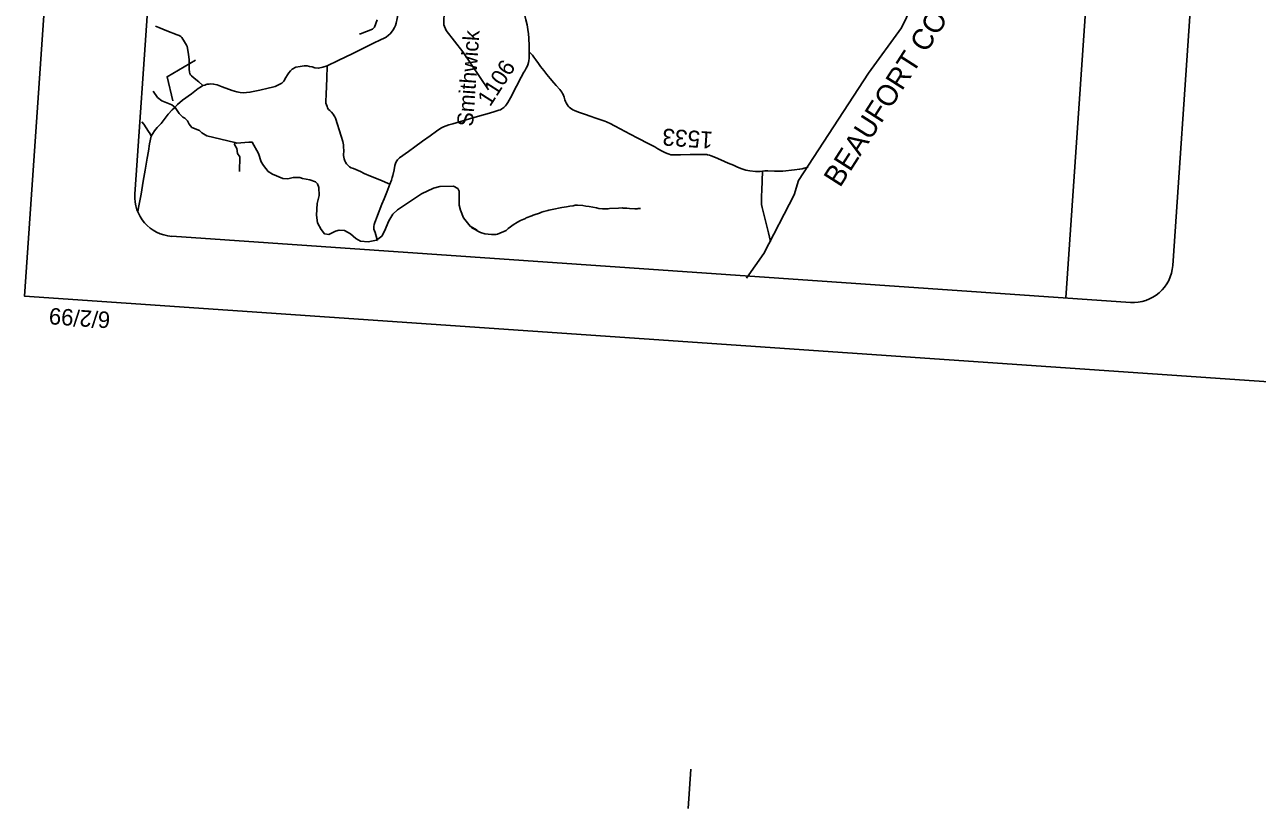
# Model space of a CAD drawing. Extents: x 2599057 to 2600057, y 728628 to 732947.
# Drawn here: x 2599056.6 to 2599398.7, y 731487.8 to 731705.3 of the extents above; entities that cross this region are included whole.
import ezdxf

# ---------------------------------------------------------------- set-up
doc = ezdxf.new("R2010")
doc.units = 0
for name, color, linetype in [('CTL Sheet Border CELL', 7, 'Continuous'), ('Old_Level_1', 7, 'Continuous'), ('Old_Level_31', 7, 'Continuous'), ('Old_Level_32', 7, 'Continuous'), ('Old_Level_50', 7, 'Continuous'), ('Old_Level_59', 7, 'Continuous')]:
    doc.layers.add(name, color=color, linetype=linetype)

msp = doc.modelspace()

# ---------------------------------------------------------------- linework, layer by layer
at = {"layer": 'CTL Sheet Border CELL'}
msp.add_line((2599240.76, 731487.81), (2599241.5, 731498.65), dxfattribs=at)
msp.add_lwpolyline([(2599146.23, 732931.19), (2599056.61, 731629.92), (2599967.49, 731567.19), (2600057.11, 732868.45)], close=True, dxfattribs=at)
at = {"layer": 'Old_Level_1'}
for p, q in [((2599108.17, 731962.68), (2599087.2, 731658.27)), ((2599345.52, 731629.45), (2599368, 731955.82)), ((2599375.24, 731638.43), (2599396.21, 731942.85)), ((2599307.81, 731720.71), (2599299.92, 731704.42)), ((2599299.92, 731704.42), (2599290.83, 731691.79)), ((2599290.83, 731691.79), (2599271.37, 731662.02)), ((2599271.37, 731662.02), (2599270.13, 731658.02)), ((2599270.13, 731658.02), (2599261.76, 731641.77)), ((2599097.42, 731646.54), (2599363.51, 731628.21)), ((2599261.76, 731641.77), (2599256.94, 731634.96))]:
    msp.add_line(p, q, dxfattribs=at)
for centre, start, end in [((2599098.18, 731657.51), 176.0601, 266.06), ((2599364.27, 731639.19), 266.06, 356.0601)]:
    msp.add_arc(centre, 11, start, end, dxfattribs=at)
at = {"layer": 'Old_Level_31'}
for p, q in [((2599098.42, 731682.31), (2599098.42, 731682.31)), ((2599261.31, 731654.36), (2599261.31, 731654.36)), ((2599154.58, 731645.25), (2599154.58, 731645.25))]:
    msp.add_line(p, q, dxfattribs=at)
msp.add_lwpolyline([(2599103.99, 731695.39), (2599096.12, 731690.83), (2599097.75, 731684.18)], dxfattribs=at)
at = {"layer": 'Old_Level_32'}
for points in [[(2599140.59, 731693.84), (2599143.66, 731695.37), (2599147.67, 731697.29), (2599153.26, 731700.01), (2599155.53, 731701.14), (2599156.17, 731701.43), (2599156.91, 731701.83), (2599157.58, 731702.32), (2599158.02, 731702.72), (2599158.41, 731703.19), (2599158.89, 731703.86), (2599159.24, 731704.46), (2599159.5, 731705.08), (2599159.69, 731705.69), (2599159.98, 731706.95), (2599160.47, 731709.67), (2599160.85, 731711.34), (2599161.37, 731713.02), (2599161.68, 731713.91)], [(2599195.11, 731708.64), (2599195.39, 731707.85), (2599195.71, 731706.65), (2599196.04, 731705.25), (2599196.3, 731703.93), (2599196.46, 731702.75), (2599196.54, 731701.57), (2599196.59, 731699.4), (2599196.62, 731697.78)], [(2599092.93, 731704.84), (2599093.86, 731704.47), (2599096.07, 731703.55), (2599098.89, 731702.48), (2599099.5, 731702.24), (2599099.93, 731701.98), (2599100.21, 731701.71), (2599101, 731700.47), (2599101.56, 731699.56), (2599101.71, 731699.17), (2599101.82, 731698.73), (2599102.11, 731697.04), (2599102.24, 731695.62), (2599102.29, 731694.35), (2599102.29, 731692.96), (2599102.35, 731692.08), (2599102.45, 731691.74), (2599102.62, 731691.38), (2599102.91, 731691.05), (2599103.61, 731690.47), (2599104.93, 731689.39), (2599106.04, 731688.37)], [(2599196.62, 731697.78), (2599196.64, 731695.95), (2599196.57, 731695.28), (2599196.47, 731694.75), (2599196.28, 731694.16), (2599196.07, 731693.67), (2599195.82, 731693.21), (2599195.46, 731692.5), (2599195.17, 731692.05), (2599194.44, 731690.68), (2599193.15, 731688.23), (2599191.42, 731684.95), (2599190.69, 731683.68), (2599190.36, 731683.13), (2599190.07, 731682.76), (2599189.62, 731682.3), (2599189.36, 731682.11), (2599189.03, 731681.91), (2599188.65, 731681.68), (2599188.23, 731681.51), (2599186.81, 731681.1), (2599185.01, 731680.56), (2599182.92, 731679.94), (2599180.09, 731679.13), (2599175.4, 731677.77), (2599174.35, 731677.44), (2599173.62, 731677.17), (2599172.85, 731676.89), (2599172.12, 731676.52), (2599170.93, 731675.69), (2599169.18, 731674.44), (2599167.02, 731672.91), (2599164.93, 731671.4), (2599163.1, 731670.08), (2599160.65, 731668.32), (2599160.35, 731668.07), (2599160.12, 731667.8), (2599159.91, 731667.49), (2599159.72, 731667.17), (2599159.55, 731666.77), (2599159.38, 731666.16), (2599159.12, 731665.03), (2599158.77, 731663.43), (2599158.64, 731662.88), (2599158.43, 731662.16), (2599157.94, 731661.02)], [(2599196.62, 731697.78), (2599196.92, 731697.46), (2599197.55, 731696.8), (2599197.96, 731696.26), (2599198.45, 731695.56), (2599199.18, 731694.52), (2599199.8, 731693.67), (2599200.66, 731692.58), (2599201.56, 731691.49), (2599202.49, 731690.38), (2599203.51, 731689.14), (2599204.13, 731688.42), (2599205.12, 731687.24), (2599205.65, 731686.52), (2599205.88, 731686.2), (2599206.05, 731685.86), (2599206.3, 731685.2), (2599206.53, 731684.42), (2599206.71, 731683.95), (2599206.89, 731683.55), (2599207.18, 731683.09), (2599207.46, 731682.7), (2599207.75, 731682.38), (2599208.06, 731682.08), (2599208.76, 731681.63), (2599209.25, 731681.41), (2599210.29, 731681), (2599212.23, 731680.35), (2599213.57, 731679.87), (2599215.17, 731679.32), (2599217.64, 731678.45), (2599218.12, 731678.29), (2599218.48, 731678.12), (2599218.9, 731677.93), (2599220.45, 731677.13), (2599224.7, 731674.89), (2599226.81, 731673.8), (2599228.11, 731673.12), (2599228.55, 731672.87), (2599229.69, 731672.28), (2599231.47, 731671.34), (2599232.35, 731670.82), (2599233.58, 731670.16), (2599234.25, 731669.82), (2599234.88, 731669.5), (2599235.46, 731669.31), (2599235.97, 731669.19), (2599236.44, 731669.12), (2599237.23, 731669.11), (2599238.66, 731669.14), (2599241.31, 731669.2), (2599243.56, 731669.26), (2599244.78, 731669.27), (2599245.42, 731669.26), (2599245.91, 731669.22), (2599246.13, 731669.19), (2599246.64, 731669.08), (2599247.11, 731668.9), (2599248.32, 731668.44), (2599249.79, 731667.81), (2599251.89, 731666.87), (2599253.37, 731666.25), (2599254.3, 731665.84), (2599254.89, 731665.58), (2599255.61, 731665.3), (2599256.18, 731665.09), (2599256.73, 731664.94), (2599257.88, 731664.74), (2599259.46, 731664.52), (2599260.71, 731664.5), (2599261.39, 731664.6)], [(2599106.04, 731688.37), (2599106.57, 731688.51), (2599106.94, 731688.63), (2599107.27, 731688.72), (2599107.84, 731688.78), (2599108.27, 731688.82), (2599109.05, 731688.79), (2599110.08, 731688.59), (2599111.4, 731688.04), (2599114.17, 731687.03), (2599115.48, 731686.67), (2599116.42, 731686.45), (2599117.34, 731686.39), (2599118.2, 731686.41), (2599119.11, 731686.5), (2599120.01, 731686.7), (2599121.86, 731687.09), (2599124.17, 731687.65), (2599125.39, 731687.89), (2599126.14, 731688.09), (2599126.69, 731688.38), (2599127.25, 731688.63), (2599127.94, 731689.06), (2599128.5, 731689.64), (2599129.08, 731690.61), (2599129.55, 731691.35), (2599129.97, 731691.88), (2599130.38, 731692.47), (2599130.83, 731692.91), (2599131.85, 731693.47), (2599133.1, 731693.7), (2599134.14, 731693.81), (2599134.97, 731693.82), (2599135.65, 731693.71), (2599136.39, 731693.53), (2599137.16, 731693.31), (2599138.16, 731693.16), (2599139.32, 731693.49), (2599140.59, 731693.84)], [(2599157.94, 731661.02), (2599155.16, 731662.22), (2599152.6, 731663.26), (2599150.86, 731664.01), (2599149.81, 731664.49), (2599147.87, 731665.33), (2599147.22, 731665.59), (2599146.8, 731665.84), (2599146.46, 731666.12), (2599146.2, 731666.36), (2599145.95, 731666.61), (2599145.66, 731667.1), (2599145.46, 731667.47), (2599145.26, 731668.01), (2599145.17, 731668.46), (2599145.13, 731668.99), (2599145.15, 731670.46), (2599145.13, 731671.15), (2599145.09, 731671.95), (2599144.87, 731672.89), (2599144.47, 731674.3), (2599142.85, 731679.33), (2599142.71, 731679.74), (2599142.51, 731680.01), (2599142.25, 731680.4), (2599141.73, 731681.01), (2599141.26, 731681.48), (2599140.98, 731681.77), (2599140.7, 731682.2), (2599140.52, 731682.59), (2599140.34, 731683.06), (2599140.24, 731683.49), (2599140.19, 731683.94), (2599140.28, 731685.96), (2599140.44, 731690.32), (2599140.59, 731693.84)], [(2599098.24, 731682.19), (2599099.06, 731683.08), (2599100.39, 731684.32), (2599102.93, 731686.11), (2599104.74, 731687.53), (2599105.4, 731687.96), (2599106.04, 731688.37)], [(2599091.69, 731674.35), (2599092.65, 731675.85), (2599093.4, 731676.72), (2599094.5, 731677.89), (2599095.56, 731679.33), (2599096.4, 731680.41), (2599097.58, 731681.6), (2599098.21, 731682.15), (2599098.24, 731682.19)], [(2599091.69, 731674.35), (2599091.41, 731675.01), (2599090.99, 731675.6), (2599089.64, 731677.68), (2599089.17, 731678.31)], [(2599089.54, 731661.86), (2599090.04, 731664.87), (2599090.6, 731668.27), (2599090.94, 731670.14), (2599091.28, 731672.18), (2599091.69, 731674.35)], [(2599261.39, 731664.6), (2599261.18, 731659.22), (2599261.14, 731657.75)], [(2599261.39, 731664.6), (2599262.02, 731664.69), (2599262.82, 731664.74), (2599264.74, 731664.66), (2599266.26, 731664.59), (2599267.06, 731664.63), (2599267.86, 731664.69), (2599269.44, 731664.87), (2599270.3, 731665), (2599271.65, 731665.15), (2599272.43, 731665.31), (2599272.97, 731665.41), (2599274.09, 731665.72)], [(2599088.02, 731653.3), (2599088.22, 731654.55), (2599088.93, 731658.23), (2599089.54, 731661.86)], [(2599157.94, 731661.02), (2599157.08, 731658.78), (2599156.34, 731656.92), (2599155.77, 731655.48), (2599154.52, 731652.29), (2599153.95, 731650.88), (2599153.76, 731650.38), (2599153.57, 731649.78), (2599153.49, 731649.29), (2599153.49, 731648.86), (2599153.52, 731648.53), (2599153.85, 731647.58), (2599154.37, 731645.96), (2599154.54, 731645.41)], [(2599261.14, 731657.75), (2599261.13, 731657.31), (2599261.09, 731656.24), (2599261.13, 731655.4), (2599261.3, 731654.57), (2599262.04, 731651.6), (2599263.03, 731647.53), (2599263.59, 731645.13)]]:
    msp.add_lwpolyline(points, dxfattribs=at)
at = {"layer": 'Old_Level_50'}
for p, q in [((2599098.39, 731682.29), (2599098.39, 731682.29)), ((2599154.6, 731645.14), (2599154.6, 731645.14))]:
    msp.add_line(p, q, dxfattribs=at)
at = {"layer": 'Old_Level_59'}
for p, q in [((2599114.91, 731672.55), (2599107.21, 731674.38)), ((2599182.22, 731648.22), (2599180.21, 731649.32))]:
    msp.add_line(p, q, dxfattribs=at)
for points in [[(2599185.3, 731687.22), (2599178.2, 731697.74), (2599173.6, 731703.61), (2599172.9, 731705.21), (2599172.94, 731707.16), (2599173.41, 731709.05), (2599174.37, 731710.5), (2599176.01, 731712.22), (2599178.01, 731712.18), (2599179.67, 731713.49), (2599180.59, 731714.79), (2599181.22, 731716.89), (2599182, 731720.65), (2599182.43, 731721.75), (2599182.64, 731721.96)], [(2599154.43, 731706.6), (2599153.68, 731704.62), (2599153.12, 731704.04), (2599149.83, 731702.69), (2599149.52, 731702.7)], [(2599107.21, 731674.38), (2599105.82, 731675.23), (2599105.11, 731675.88), (2599103.03, 731676.77), (2599102.29, 731677.7), (2599101.82, 731678.61), (2599101.05, 731679.32), (2599100.47, 731679.62), (2599099.52, 731680.62), (2599098.39, 731682.3), (2599097.47, 731683.07), (2599094.67, 731684.1), (2599093.49, 731685.05), (2599092.25, 731686.79)], [(2599116.25, 731664.49), (2599116.36, 731668.57), (2599115.65, 731669.5), (2599115.47, 731670.91), (2599114.84, 731672.05), (2599114.91, 731672.55)], [(2599133.76, 731662.63), (2599132.96, 731662.9), (2599131.17, 731662.88), (2599129.62, 731662.51), (2599128.24, 731662.57), (2599125.38, 731663.83), (2599124.16, 731664.56), (2599122.85, 731666.19), (2599122.28, 731667.22), (2599121.53, 731669.5), (2599119.79, 731672.65), (2599118.84, 731672.7), (2599115.49, 731672.41), (2599114.91, 731672.55)], [(2599180.21, 731649.32), (2599178.42, 731651.7), (2599177.53, 731653.81), (2599177.22, 731655.23), (2599177.21, 731659.09), (2599176.82, 731659.84), (2599175.63, 731660.45), (2599171.87, 731660.41), (2599170.04, 731659.88), (2599166.78, 731658.3), (2599160.04, 731653.93), (2599158.82, 731652.7), (2599157.72, 731650.8), (2599156.51, 731648), (2599155.69, 731646.59), (2599154.26, 731645.43), (2599151.91, 731645.04), (2599149.86, 731645.2), (2599148.56, 731645.93), (2599147.08, 731647.23), (2599145.34, 731648.15), (2599143.86, 731648.28), (2599142.89, 731647.93), (2599141.03, 731647.01), (2599139.79, 731647.25), (2599138.88, 731648.4), (2599137.92, 731650.24), (2599137.65, 731652.38), (2599137.81, 731655.67), (2599138.3, 731657.89), (2599138.26, 731660.13), (2599137.87, 731661.09), (2599137.33, 731661.62), (2599135.72, 731662.2), (2599133.76, 731662.63)], [(2599222.69, 731654.4), (2599222.4, 731654.43), (2599221.42, 731654.32), (2599218.95, 731654.24), (2599218.53, 731654.2), (2599217.8, 731654.13), (2599217, 731654.13), (2599215.97, 731654.27), (2599215.31, 731654.49), (2599213.26, 731654.86), (2599212.36, 731654.91), (2599211.5, 731655.12), (2599210, 731655.18), (2599209.84, 731655.16), (2599209.43, 731655.17), (2599208.87, 731655.04), (2599207.94, 731654.9), (2599206.98, 731654.69), (2599205.72, 731654.52), (2599203.04, 731654.01), (2599202.1, 731653.82), (2599201.84, 731653.7), (2599200.67, 731653.46), (2599200.05, 731653.27), (2599199.45, 731653), (2599197.98, 731652.47), (2599197.71, 731652.4), (2599197.34, 731652.19), (2599195.81, 731651.64), (2599195.6, 731651.51), (2599194.24, 731650.93), (2599193.35, 731650.49), (2599192.21, 731649.75), (2599191.4, 731649.17), (2599190.79, 731648.72), (2599190.21, 731648.18), (2599187.87, 731647.14), (2599187.4, 731647.04), (2599186.13, 731647.05), (2599184.32, 731647.26), (2599183.11, 731647.61), (2599182.55, 731647.88), (2599182.35, 731647.96)], [(2599222.69, 731654.4), (2599223.76, 731654.34), (2599224.43, 731654.28), (2599225.94, 731654.21), (2599226.6, 731654.18), (2599226.85, 731654.26), (2599227.53, 731654.25)], [(2599182.35, 731647.96), (2599181.91, 731648.22), (2599181.8, 731648.33), (2599181.11, 731648.69), (2599180.82, 731648.82), (2599180.21, 731649.32)]]:
    msp.add_lwpolyline(points, dxfattribs=at)

# ---------------------------------------------------------------- texts
at = {"layer": 'CTL Sheet Border CELL'}
msp.add_text('6/2/99', height=4.565, rotation=176.0601, dxfattribs=at).set_placement((2599080.49, 731625.55))
at = {"layer": 'Old_Level_1'}
for s, height, rotation, p in [('BEAUFORT COUNTY', 5.797, 57.3831, (2599282.89, 731659.86)), ('Smithwick', 4.446, 86.0601, (2599181.03, 731676.9)), ('1106', 4.509, 57.3831, (2599185.77, 731682.3)), ('1533', 4.693, 176.0601, (2599247.72, 731675.51))]:
    msp.add_text(s, height=height, rotation=rotation, dxfattribs=at).set_placement(p)

doc.saveas('drawing.dxf')
